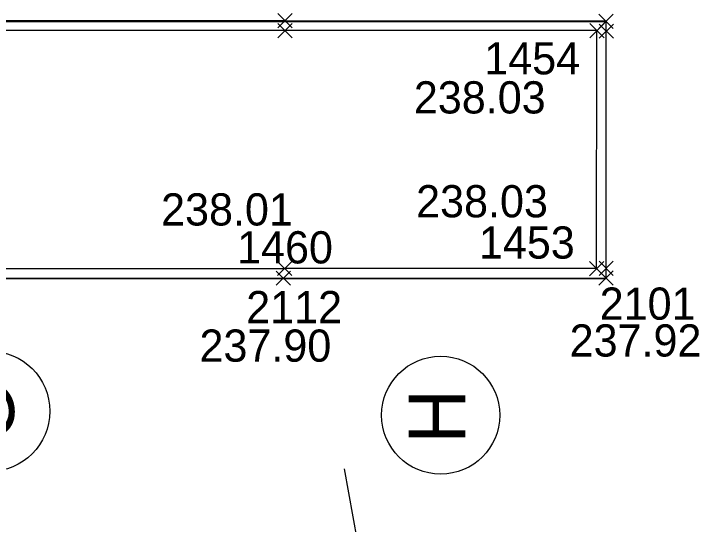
# Model space of a CAD drawing. Extents: x -264205 to -263659, y -1242401 to -1241986.
# Drawn here: x -263876.15 to -263865.52, y -1242082.19 to -1242074.26 of the extents above; entities that cross this region are included whole.
import ezdxf

# ---------------------------------------------------------------- set-up
doc = ezdxf.new("R2010")
doc.units = 0
for name, color, linetype in [('BOD_CISLO_2-2', 7, 'Continuous'), ('BOD_SYMBOL_2-2', 7, 'Continuous'), ('BOD_VYSKA_2-2', 7, 'Continuous'), ('HESCON_OSI_STAVBY_KFA', 7, 'Continuous'), ('PROJEKT_OBRUBNIKY_KOMUNIKACIE', 7, 'Continuous'), ('SITUACIA_DSP_2D', 7, 'Continuous'), ('SO_20-4_OBRUBNIKY_DOLNA_HRANA', 7, 'Continuous'), ('SO_20-4_OBRUBNIKY_HORNA_HRANA', 7, 'Continuous')]:
    doc.layers.add(name, color=color, linetype=linetype)

msp = doc.modelspace()

# ---------------------------------------------------------------- linework, layer by layer
at = {"layer": 'BOD_SYMBOL_2-2'}
for p, q in [((-263872.055, -1242074.484), (-263871.834, -1242074.262)), ((-263871.834, -1242074.484), (-263872.055, -1242074.262)), ((-263867.072, -1242074.49), (-263866.851, -1242074.269)), ((-263866.851, -1242074.49), (-263867.072, -1242074.269)), ((-263872.054, -1242074.636), (-263871.833, -1242074.414)), ((-263871.833, -1242074.636), (-263872.054, -1242074.414)), ((-263867.214, -1242074.636), (-263866.992, -1242074.414)), ((-263866.992, -1242074.636), (-263867.214, -1242074.414)), ((-263867.068, -1242074.644), (-263866.847, -1242074.424)), ((-263866.847, -1242074.644), (-263867.068, -1242074.424)), ((-263872.058, -1242078.329), (-263871.837, -1242078.109)), ((-263871.837, -1242078.329), (-263872.058, -1242078.109)), ((-263867.219, -1242078.333), (-263866.997, -1242078.112)), ((-263866.997, -1242078.333), (-263867.219, -1242078.112)), ((-263867.071, -1242078.326), (-263866.85, -1242078.106)), ((-263866.85, -1242078.326), (-263867.071, -1242078.106)), ((-263872.078, -1242078.481), (-263871.856, -1242078.259)), ((-263871.856, -1242078.481), (-263872.078, -1242078.259)), ((-263867.073, -1242078.478), (-263866.851, -1242078.258)), ((-263866.851, -1242078.478), (-263867.073, -1242078.258))]:
    msp.add_line(p, q, dxfattribs=at)
at = {"layer": 'HESCON_OSI_STAVBY_KFA'}
for centre, radius in [((-263876.528, -1242080.436), 0.935), ((-263869.528, -1242080.498), 0.916)]:
    msp.add_circle(centre, radius, dxfattribs=at)
at = {"layer": 'PROJEKT_OBRUBNIKY_KOMUNIKACIE'}
msp.add_lwpolyline([(-263881.968, -1242074.382), (-263866.968, -1242074.382), (-263866.968, -1242078.382), (-263881.968, -1242078.382), (-263881.968, -1242074.382)], dxfattribs=at)
at = {"layer": 'SITUACIA_DSP_2D'}
for p, q in [((-263881.968, -1242074.382), (-263866.968, -1242074.382)), ((-263866.968, -1242074.382), (-263866.968, -1242078.382)), ((-263866.968, -1242078.382), (-263881.968, -1242078.382)), ((-263869.881, -1242087.633), (-263871.02, -1242081.332))]:
    msp.add_line(p, q, dxfattribs=at)
at = {"layer": 'SO_20-4_OBRUBNIKY_DOLNA_HRANA'}
msp.add_line((-263871.967, -1242078.37), (-263866.962, -1242078.368), dxfattribs=at)
msp.add_lwpolyline([(-263866.962, -1242078.368), (-263866.96, -1242078.216), (-263866.958, -1242074.534), (-263866.961, -1242074.379), (-263871.944, -1242074.373), (-263876.968, -1242074.373), (-263881.942, -1242074.377), (-263881.947, -1242074.531), (-263881.947, -1242078.206), (-263881.943, -1242078.363), (-263876.946, -1242078.364), (-263871.967, -1242078.37)], dxfattribs=at)
at = {"layer": 'SO_20-4_OBRUBNIKY_HORNA_HRANA'}
msp.add_line((-263867.108, -1242078.222), (-263871.948, -1242078.219), dxfattribs=at)
msp.add_lwpolyline([(-263867.108, -1242078.222), (-263867.103, -1242074.525), (-263871.943, -1242074.525), (-263876.963, -1242074.523), (-263881.8, -1242074.524), (-263881.802, -1242078.218), (-263876.943, -1242078.218), (-263871.948, -1242078.219)], dxfattribs=at)

# ---------------------------------------------------------------- texts
at = {"layer": 'BOD_CISLO_2-2'}
for s, p in [('1454', (-263868.852, -1242075.205)), ('1460', (-263872.687, -1242078.141)), ('1453', (-263868.935, -1242078.066)), ('2101', (-263867.061, -1242079.015)), ('2112', (-263872.545, -1242079.069))]:
    msp.add_text(s, height=0.5, dxfattribs=at).set_placement(p)
at = {"layer": 'BOD_VYSKA_2-2'}
for s, p in [('238.03', (-263869.944, -1242075.812)), ('238.03', (-263869.909, -1242077.425)), ('238.01', (-263873.866, -1242077.552)), ('237.92', (-263867.527, -1242079.587)), ('237.90', (-263873.27, -1242079.667))]:
    msp.add_text(s, height=0.5, dxfattribs=at).set_placement(p)
at = {"layer": 'HESCON_OSI_STAVBY_KFA'}
for s, p in [('G', (-263876.147, -1242080.911)), ('H', (-263869.147, -1242080.939))]:
    msp.add_text(s, height=0.875, rotation=90, dxfattribs=at).set_placement(p)

doc.saveas('drawing.dxf')
